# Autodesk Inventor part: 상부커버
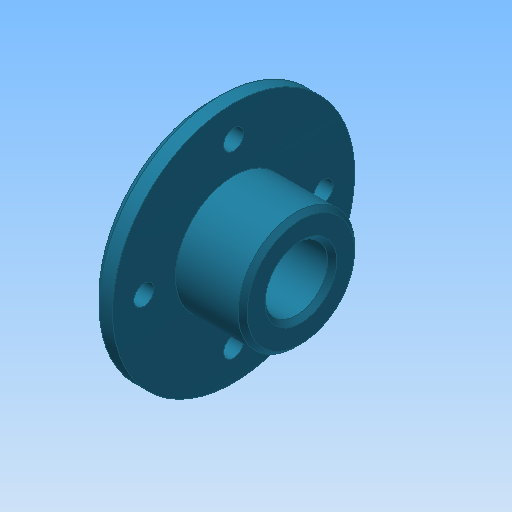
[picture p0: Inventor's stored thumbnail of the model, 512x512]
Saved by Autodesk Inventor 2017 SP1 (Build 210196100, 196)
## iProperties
Created: 2015-09
Part Number: 상부커버
Material: 알루미늄 6061
Document SubType Name: Modeling
Designer: mduedu
Density: 1 g/cm^3
Appearance: 터키옥색
Author: mduedu
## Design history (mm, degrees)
sketch "스케치1"
  geometry: L1 (-10, 0)-(10, 0); L2 (-10, 0)-(-10, 27); L3 (-10, 27)-(-5, 27); L4 (-5, 27)-(-5, 13); L5 (-5, 13)-(10, 13); L6 (10, 13)-(10, 0); 2 further points
  constraints: 12 end point, 2 parallel, 2 perpendicular, 1 coincident, 1 horizontal, 1 midpoint, 1 vertical
  dimensions: "d0" = 20 distance of L1.start L1.end; "d2" = 5 distance of L2.end L3.end; "d3" = 26 diameter of L5 L1; "d4" = 54 diameter of L3 L1
revolve "회전1" sketch "스케치1" stored, may be unused: angle "d5" = 90 deg
hole "구멍1" diameter "d8" = 14; stored, may be unused: countersink angle "d12" = 90 deg, drill point angle "d14" = 118 deg; dims "d6" = 10, "d7" = 10, "d9" = 6, "d10" = 4, "d11" = 2, "d13" = 8
chamfer "모따기1" distance "d15" = 1; stored, may be unused: second distance "d16" = 2, angle "d17" = 45 deg
chamfer "모따기2" distance "d18" = 2; stored, may be unused: second distance "d19" = 2, angle "d20" = 45 deg
sketch "스케치2" dims "d21" = 40
  geometry: 6 further points
  constraints: 2 vertical alignment, 1 coincident, 7 other
  dimensions: "d25" = 360 deg dimension on point (0, 0) point (0, 20) (derived)
sketch "스케치3"
  geometry: 4 further points
hole "구멍2" sketch "스케치3" at (0, 20), (-20, 0), (20, 0), (0, -20) diameter "d27" = 4.5; stored, may be unused: countersink angle "d31" = 90 deg, drill point angle "d33" = 0 deg; dims "d28" = 6, "d29" = 4, "d30" = 2, "d32" = 8
node "솔리드1"
